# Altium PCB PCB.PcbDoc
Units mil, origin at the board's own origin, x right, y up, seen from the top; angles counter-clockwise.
Board outline 6444.88 x 3495 mil, 2 copper layers (Top Layer, Bottom Layer); 152 components, 81 nets, 447 pads, 87 vias.
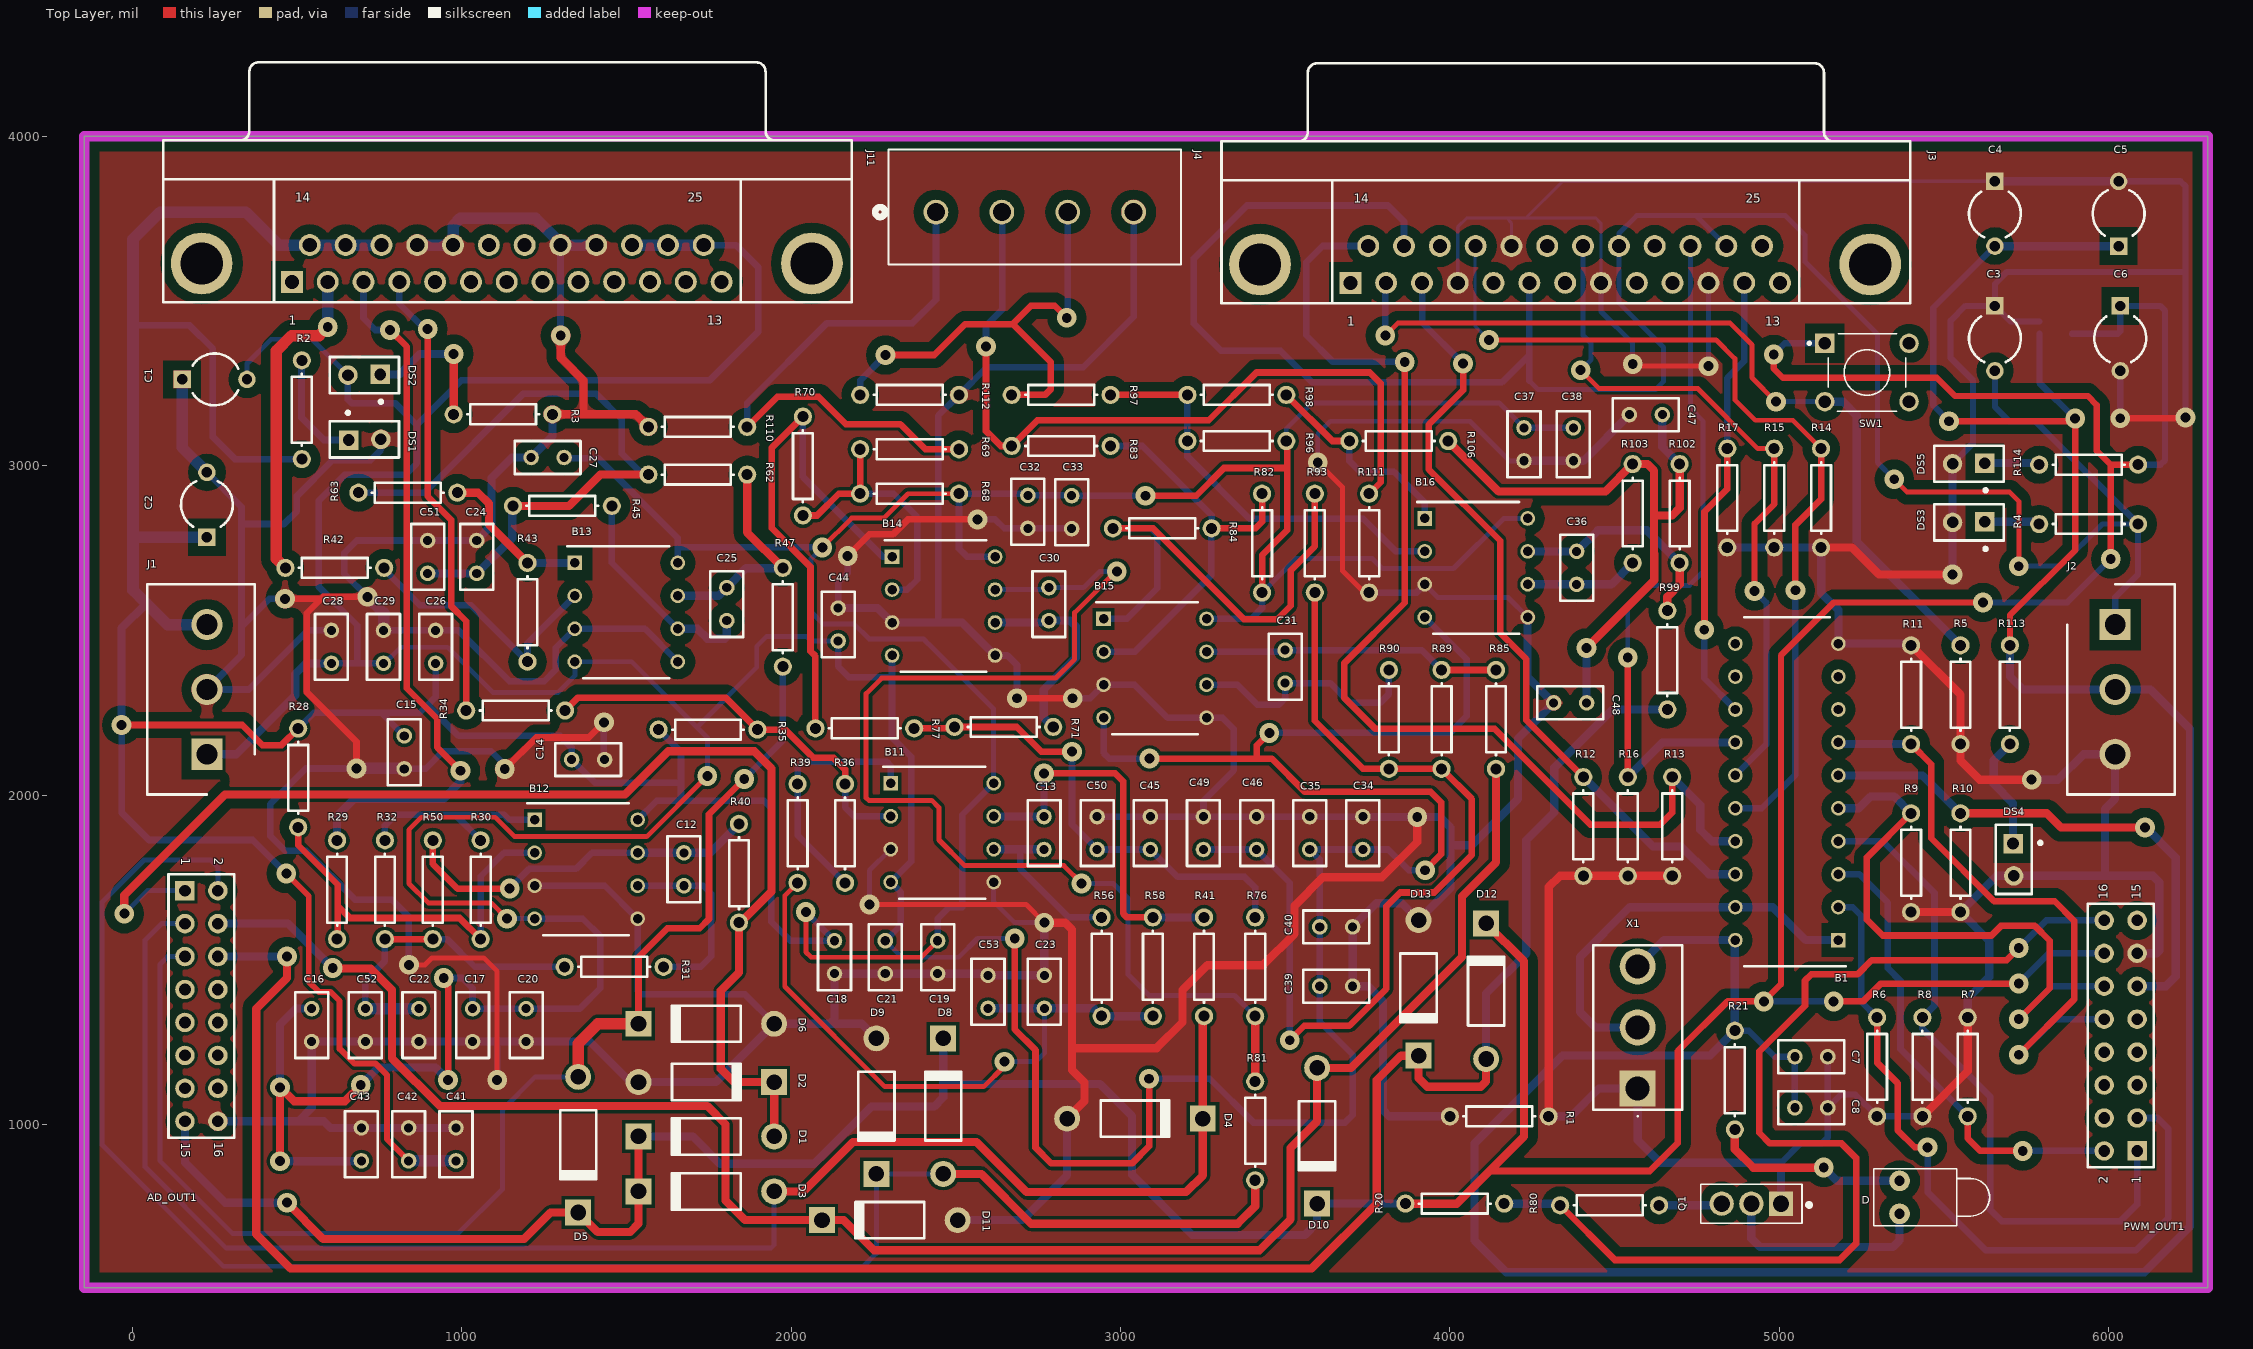
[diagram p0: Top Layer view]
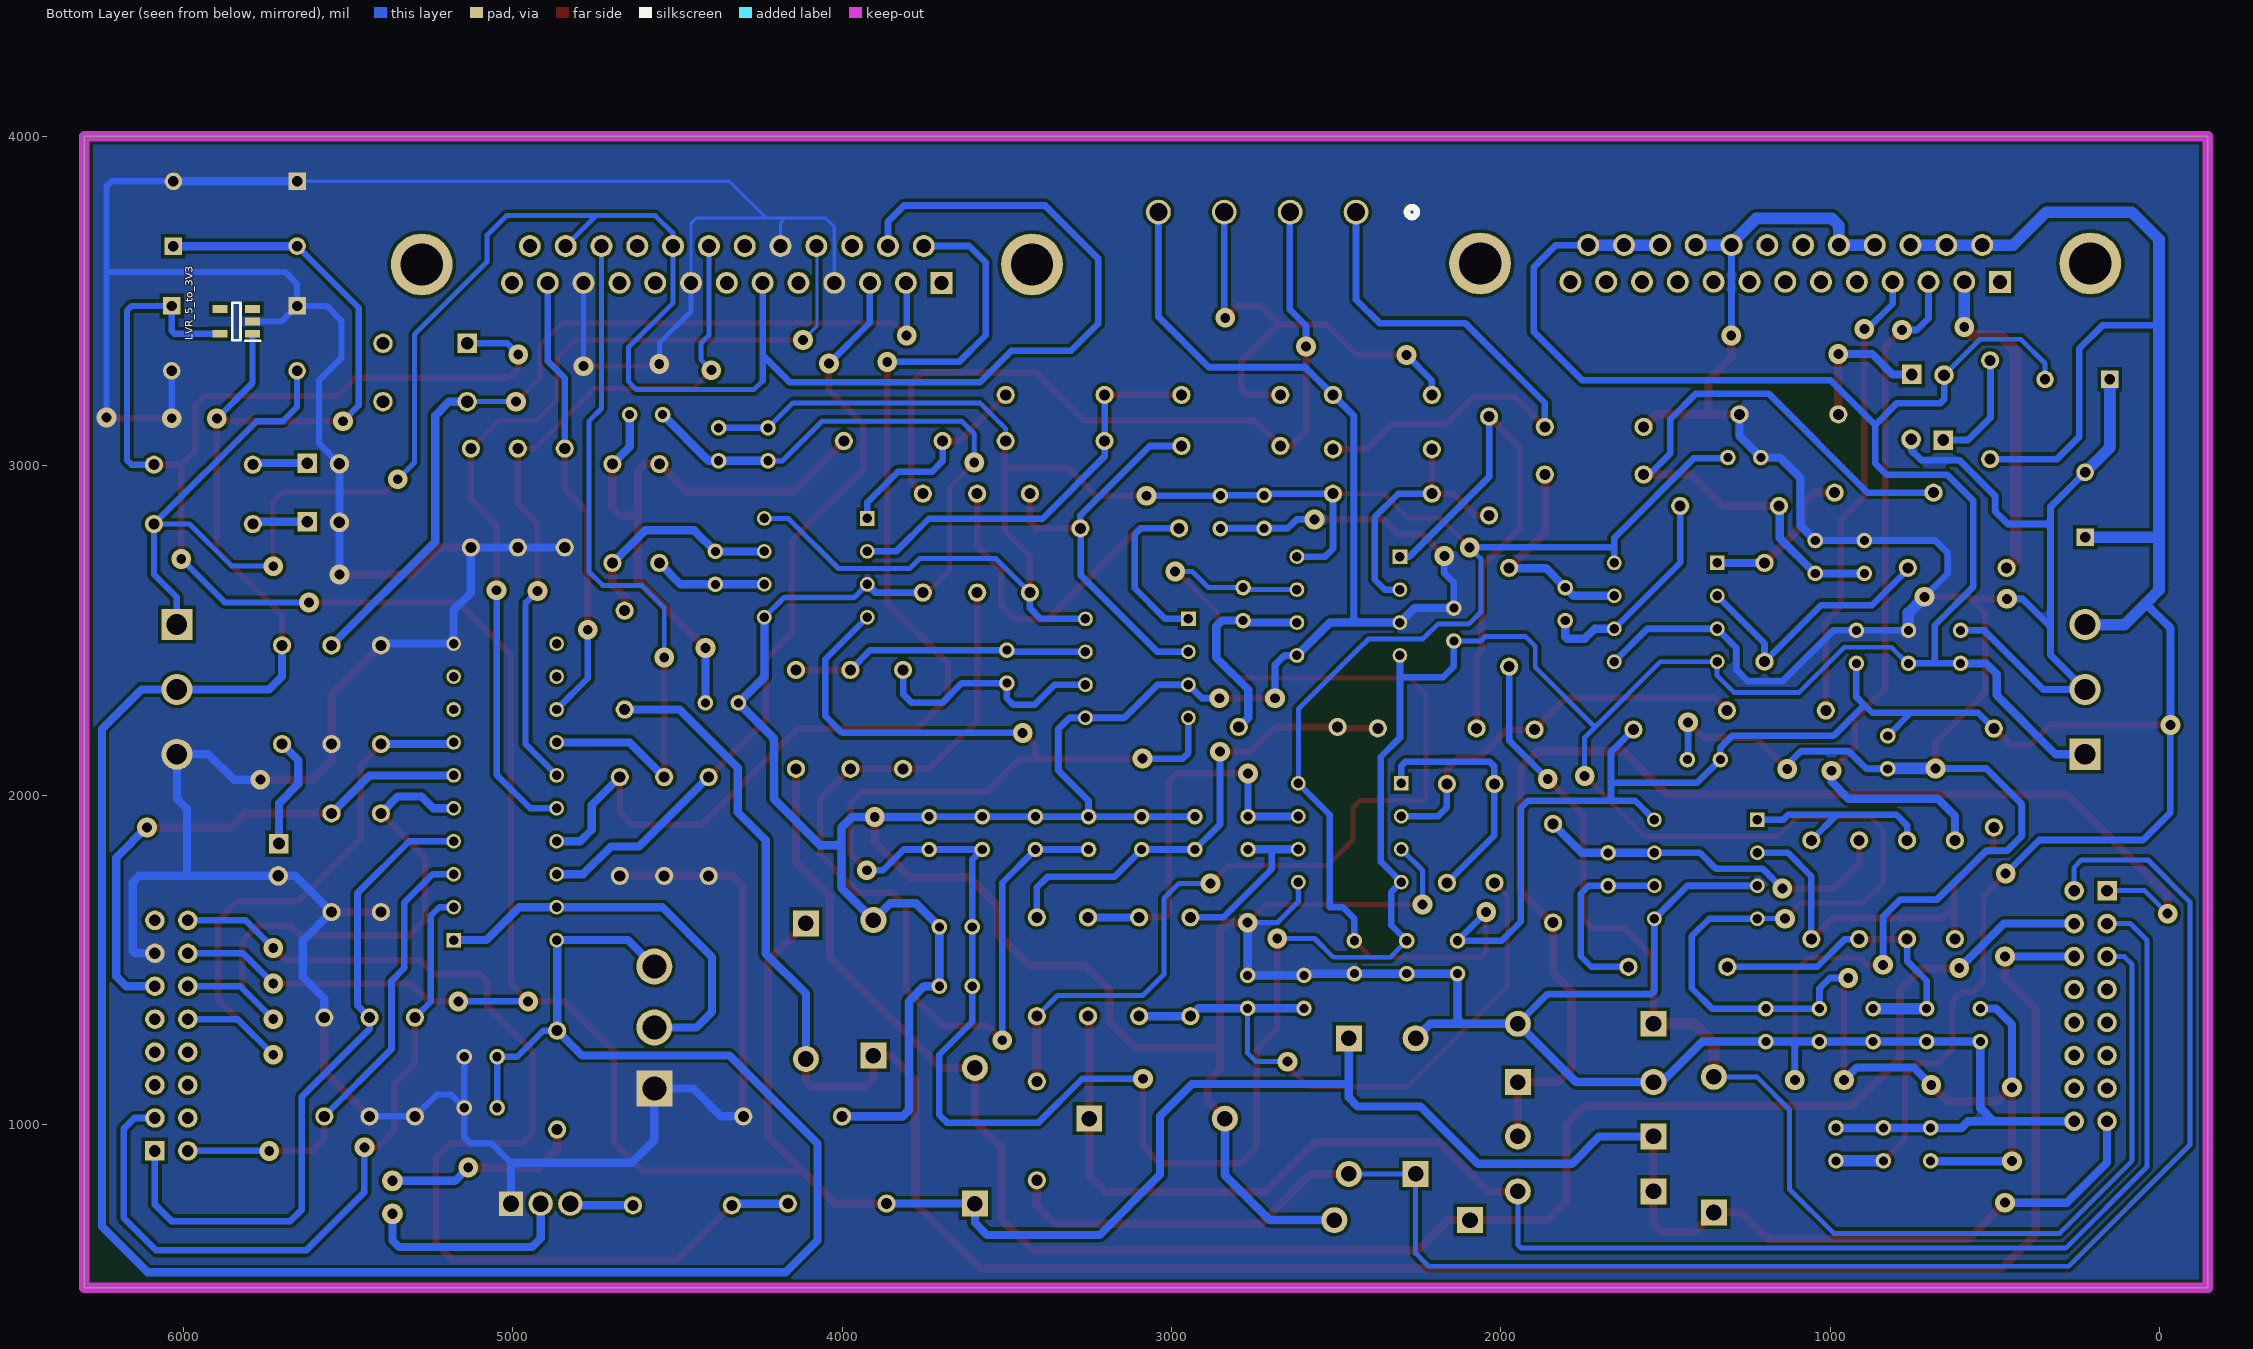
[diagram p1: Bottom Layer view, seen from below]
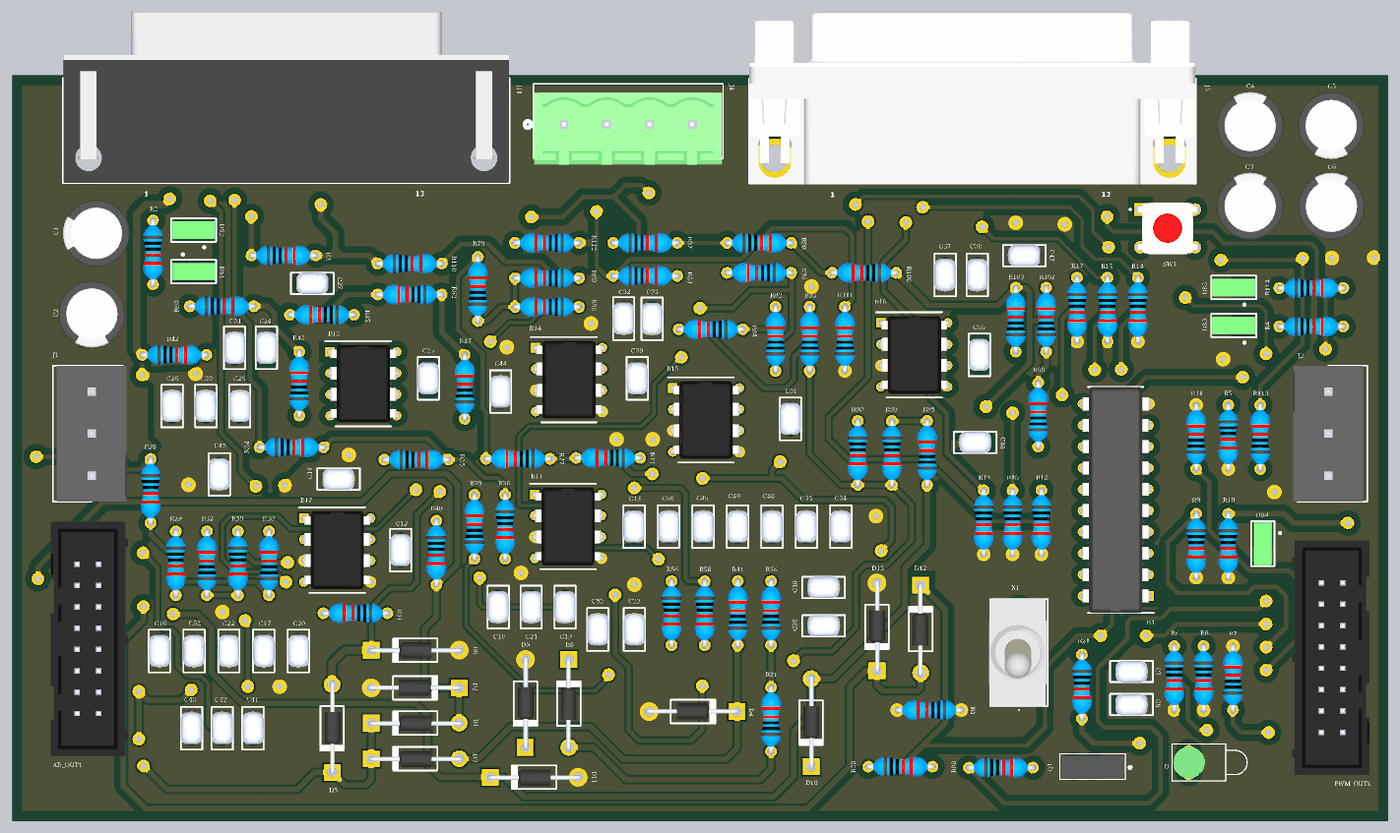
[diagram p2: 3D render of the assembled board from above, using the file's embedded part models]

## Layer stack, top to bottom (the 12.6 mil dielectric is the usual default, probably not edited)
Top Solder: solder mask 0.4, Solder Resist, Dk 3.5
Top Layer: signal copper 1.4
Dielectric 1: dielectric 12.6, FR-4, Dk 4.8
Bottom Layer: signal copper 1.4
Bottom Solder: solder mask 0.4, Solder Resist, Dk 3.5

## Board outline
-144.88,505 6300,505 6300,4000 -144.88,4000

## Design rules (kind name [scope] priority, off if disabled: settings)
Clearance "my clearance" [InNamedPolygon('Top Layer-No Net')] p1: gap=30
Clearance Clearance_1 [(InPadClass('All Pads')) vs (InPadClass('All Pads'))] p2: gap=10
Clearance [All] p3: gap=10
HoleSize [All] p1: absolutevalues=TRUE maxlimit=150 minlimit=1 maxpercent=80.000 minpercent=20.000
PolygonConnect [All] p1: connectstyle=Direct reliefconductorwidth=10 reliefentries=4 polygonreliefangle="90 Angle" airgapwidth=10
RoutingVias [All] p1: holewidth=30 width=60 viastyle="Through Hole" minholewidth=30 minwidth=60 maxholewidth=30 maxwidth=60
SolderMaskExpansion [All] p1: expansion=4
Width [All] p1: maxlimit=50 minlimit=10 preferedwidth=10
29 further rules are at their usual default settings.

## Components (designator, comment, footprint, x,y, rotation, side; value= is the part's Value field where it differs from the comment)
AD_OUT1 "Header 8X2" HDR2X8 160.22,1710 r270 top
B1 "SN74HCT541N" DIP794W53P254L2540H508Q20N 5023,2010 r180 top
B11 "TL082IP" DIP794W53P254L959H508Q8N 2459,1886 r0 top
B12 "TL082IP" DIP794W53P254L959H508Q8N 1378,1775 r0 top
B13 "TL082IP" DIP794W53P254L959H508Q8N 1500,2555 r0 top
B14 "TL082IP" DIP794W53P254L959H508Q8N 2463,2574 r0 top
B15 "TL082IP" DIP794W53P254L959H508Q8N 3105,2385 r0 top
B16 "TL082IP" DIP794W53P254L959H508Q8N 4080,2690 r0 top
C1 "Cap Pol" CAPR5-4X5 250,3262 r0 top
C2 "Cap Pol" CAPR5-4X5 226.97,2881.57 r90 top
C3 "Cap Pol" CAPR5-4X5 5654.5,3386.57 r270 top
C4 "Cap Pol" CAPR5-4X5 5654.5,3765 r270 top
C5 "Cap Pol" CAPR5-4X5 6030,3765 r90 top
C6 "Cap Pol" CAPR5-4X5 6035,3386.57 r270 top
C7 "Cap No Pol" RAD-0.1 5097,1206 r0 top
C8 "Cap No Pol" RAD-0.1 5097,1051 r0 top
C12 "Cap No Pol" RAD-0.1 1675,1775 r270 top
C13 "Cap No Pol" RAD-0.1 2768,1885 r270 top
C14 "Cap No Pol" RAD-0.1 1384,2108 r0 top
C15 "Cap No Pol" RAD-0.1 826,2130 r270 top
C16 "Cap No Pol" RAD-0.1 545,1302 r90 top
C17 "Cap No Pol" RAD-0.1 1033.25,1302 r90 top
C18 "Cap No Pol" RAD-0.1 2132,1508 r270 top
C19 "Cap No Pol" RAD-0.1 2445,1508 r270 top
C20 "Cap No Pol" RAD-0.1 1196,1302 r90 top
C21 "Cap No Pol" RAD-0.1 2286,1508 r90 top
C22 "Cap No Pol" RAD-0.1 870.5,1302 r270 top
C23 "Cap No Pol" RAD-0.1 2769,1403 r90 top
C24 "Cap No Pol" RAD-0.1 1046,2723 r90 top
C25 "Cap No Pol" RAD-0.1 1805,2580 r270 top
C26 "Cap No Pol" RAD-0.1 921,2450 r90 top
C27 "Cap No Pol" RAD-0.1 1261,3025 r180 top
C28 "Cap No Pol" RAD-0.1 605,2450 r270 top
C29 "Cap No Pol" RAD-0.1 763,2450 r270 top
C30 "Cap No Pol" RAD-0.1 2783,2580 r270 top
C31 "Cap No Pol" RAD-0.1 3500,2390 r270 top
C32 "Cap No Pol" RAD-0.1 2719,2860 r270 top
C33 "Cap No Pol" RAD-0.1 2852,2859 r270 top
C34 "Cap No Pol" RAD-0.1 3736,1885 r270 top
C35 "Cap No Pol" RAD-0.1 3574.67,1885 r270 top
C36 "Cap No Pol" RAD-0.1 4385,2690 r270 top
C37 "Cap No Pol" RAD-0.1 4225,3065 r270 top
C38 "Cap No Pol" RAD-0.1 4375,3065 r270 top
C39 "Cap No Pol" RAD-0.1 3655,1420 r180 top
C40 "Cap No Pol" RAD-0.1 3655,1600 r180 top
C41 "Cap No Pol" RAD-0.1 983,940 r90 top
C42 "Cap No Pol" RAD-0.1 839,940 r90 top
C43 "Cap No Pol" RAD-0.1 696,940 r270 top
C44 "Cap No Pol" RAD-0.1 2143,2518 r270 top
C45 "Cap No Pol" RAD-0.1 3090.67,1885 r90 top
C46 "Cap No Pol" RAD-0.1 3413.33,1885 r90 top
C47 "Cap No Pol" RAD-0.1 4595,3155 r180 top
C48 "Cap No Pol" RAD-0.1 4365,2280 r180 top
C49 "Cap No Pol" RAD-0.1 3252,1885 r90 top
C50 "Cap No Pol" RAD-0.1 2929.33,1885 r90 top
C51 "Cap No Pol" RAD-0.1 897,2723 r90 top
C52 "Cap No Pol" RAD-0.1 707.75,1302 r270 top
C53 "Cap No Pol" RAD-0.1 2598,1403 r90 top
D "LED1" LED-1 5365,779.23 r0 top
D1 "Diode BAT54" DO-204AL 1743,964 r180 top
D2 "Diode BAT54" DO-204AL 1743,1129 r0 top
D3 "Diode BAT54" DO-204AL 1743,797 r180 top
D4 "Diode BAT54" DO-204AL 3044,1018 r0 top
D5 "Diode BAT54" DO-204AL 1354,939 r270 top
D6 "Diode BAT54" DO-204AL 1743,1306 r180 top
D8 "Diode BAT54" DO-204AL 2462,1056 r90 top
D9 "Diode BAT54" DO-204AL 2259,1056 r270 top
D10 "Diode BAT54" DO-204AL 3597,966 r270 top
D11 "Diode BAT54" DO-204AL 2300,710 r180 top
D12 "Diode BAT54" DO-204AL 4110,1405 r90 top
D13 "Diode BAT54" DO-204AL 3905,1415 r270 top
DS1 "Lamp" PIN2 655,3080 r0 top
DS2 "Lamp" PIN2 755,3275 r180 top
DS3 "Lamp" PIN2 5626,2828 r180 top
DS4 "Lamp" PIN2 5711.64,1855 r270 top
DS5 "Lamp" PIN2 5626,3006 r180 top
J1 "CTB9302_3" SHDR3W100P0X500_1X3_1620X830X1230P 226.97,2124 r90 top
J2 "CTB9302_3" SHDR3W100P0X500_1X3_1620X830X1230P 6019.41,2517.7 r270 top
J3 "D Female Connector 25" DSUB1.385-2H25B 4350,3985 r0 top
J4 "1755752" CONN_1924321 3040,3770 r0 top
J11 "D Connector 25" DSUB1.385-2H25A 1137.13,3987.99 r0 top
LVR_5_to_3V3 "ADP151AUJZ-3.3-R7" SOT95P280X100-5N 5839,3438 r0 bottom
PWM_OUT1 "Header 8X2" HDR2X8 6086.16,919.97 r90 top
Q1 "BD135" TO229P780X300X2000-3 5005.31,760 r180 top
R1 "Res1" AXIAL-0.3 4150,1025 r0 top
R2 "Res1" AXIAL-0.3 515,3170 r90 top
R3 "Res1" AXIAL-0.3 1126,3156 r180 top
R4 "Res1" AXIAL-0.3 5939,2823 r180 top
R5 "Res1" AXIAL-0.3 5550,2305 r90 top
R6 "Res1" AXIAL-0.3 5297,1175 r90 top
R7 "Res1" AXIAL-0.3 5572,1175 r270 top
R8 "Res1" AXIAL-0.3 5434.5,1175 r90 top
R9 "Res1" AXIAL-0.3 5400,1795 r90 top
R10 "Res1" AXIAL-0.3 5550,1795 r90 top
R11 "Res1" AXIAL-0.3 5400,2305 r270 top
R12 "Res1" AXIAL-0.3 4405,1905 r90 top
R13 "Res1" AXIAL-0.3 4675,1905 r90 top
R14 "Res1" AXIAL-0.3 5127,2902 r90 top
R15 "Res1" AXIAL-0.3 4984.5,2902 r90 top
R16 "Res1" AXIAL-0.3 4540,1905 r90 top
R17 "Res1" AXIAL-0.3 4842,2902 r90 top
R20 "Res1" AXIAL-0.3 4015,760 r180 top
R21 "Res1" AXIAL-0.3 4865,1135 r90 top
R28 "Res1" AXIAL-0.3 504,2052.38 r90 top
R29 "Res1" AXIAL-0.3 622,1713 r90 top
R30 "Res1" AXIAL-0.3 1058,1713 r270 top
R31 "Res1" AXIAL-0.3 1463,1479 r0 top
R32 "Res1" AXIAL-0.3 767.33,1713 r270 top
R34 "Res1" AXIAL-0.3 1164,2257 r180 top
R35 "Res1" AXIAL-0.3 1748,2199 r180 top
R36 "Res1" AXIAL-0.3 2164,1884 r90 top
R39 "Res1" AXIAL-0.3 2020,1884 r270 top
R40 "Res1" AXIAL-0.3 1842,1763 r90 top
R41 "Res1" AXIAL-0.3 3253.67,1479 r270 top
R42 "Res1" AXIAL-0.3 615,2690 r180 top
R43 "Res1" AXIAL-0.3 1200,2555 r270 top
R45 "Res1" AXIAL-0.3 1306,2878 r0 top
R47 "Res1" AXIAL-0.3 1975,2540 r270 top
R50 "Res1" AXIAL-0.3 912.67,1713 r90 top
R56 "Res1" AXIAL-0.3 2943,1479 r90 top
R58 "Res1" AXIAL-0.3 3098.33,1479 r90 top
R62 "Res1" AXIAL-0.3 1717,2973 r0 top
R63 "Res1" AXIAL-0.3 837,2918 r180 top
R68 "Res1" AXIAL-0.3 2360,2915 r0 top
R69 "Res1" AXIAL-0.3 2360,3050 r0 top
R70 "Res1" AXIAL-0.3 2036,2999 r270 top
R71 "Res1" AXIAL-0.3 2646,2207 r0 top
R76 "Res1" AXIAL-0.3 3409,1479 r270 top
R77 "Res1" AXIAL-0.3 2224,2203 r0 top
R80 "Res1" AXIAL-0.3 4485,755 r180 top
R81 "Res1" AXIAL-0.3 3409,981 r270 top
R82 "Res1" AXIAL-0.3 3430,2765 r270 top
R83 "Res1" AXIAL-0.3 2820,3060 r180 top
R84 "Res1" AXIAL-0.3 3127,2810 r0 top
R85 "Res1" AXIAL-0.3 4140,2230 r270 top
R89 "Res1" AXIAL-0.3 3975,2230 r90 top
R90 "Res1" AXIAL-0.3 3815,2230 r90 top
R93 "Res1" AXIAL-0.3 3590,2765 r270 top
R96 "Res1" AXIAL-0.3 3353.33,3075 r0 top
R97 "Res1" AXIAL-0.3 2820,3215 r180 top
R98 "Res1" AXIAL-0.3 3353.33,3215 r180 top
R99 "Res1" AXIAL-0.3 4660,2410 r270 top
R102 "Res1" AXIAL-0.3 4697.5,2855 r270 top
R103 "Res1" AXIAL-0.3 4555,2855 r270 top
R106 "Res1" AXIAL-0.3 3845,3075 r0 top
R110 "Res1" AXIAL-0.3 1717,3118 r180 top
R111 "Res1" AXIAL-0.3 3755,2765 r270 top
R112 "Res1" AXIAL-0.3 2360,3215 r0 top
R113 "Res1" AXIAL-0.3 5700,2305 r270 top
R114 "Res1" AXIAL-0.3 5939,3003 r180 top
SW1 "1825910-6" SW_1825910-6-4 5266,3283 r0 top
X1 "1MS1T1B1M2QES" 1MS1T1B1M2QES 4570,1109.92 r0 top

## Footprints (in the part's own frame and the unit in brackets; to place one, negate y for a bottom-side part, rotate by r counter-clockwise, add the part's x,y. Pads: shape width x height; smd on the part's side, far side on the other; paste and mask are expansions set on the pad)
1MS1T1B1M2QES [mm]
  rect 2.775x2.775 hole 1.85: 1(0,0)
  round 2.775 hole 1.85: 2(0,4.7) 3(0,9.4)
  silkscreen extent -3.43,-2.2 3.43,11.05, body extent -3.56,-1.65 3.3,11.05, height 27.73
AXIAL-0.3 [mm]
  round 1.4 hole 0.85: 1(-3.81,0) 2(3.81,0)
  silkscreen extent -2.77,-0.76 2.77,0.76, body extent -4.11,-1.2 4.11,1.2, height 2.6
CAPR5-4X5 [mm]
  rect 1.35x1.35 hole 0.8: 1(-2.5,0)
  round 1.35 hole 0.8: 2(2.5,0)
  silkscreen extent -1.69,-2 1.82,2, body extent -4,-4.05 4,3.95, height 11.75
CONN_1924321 [mil]
  round 75 / inner round 60 / far side round 75 hole 55 paste-37.5 mask+0: 1(-600,0) 2(-400,0) 3(-200,0) 4(0,0)
  silkscreen extent -784,-159 144,190, body extent -740,-189 139,150, height 492
DIP794W53P254L959H508Q8N [mm]
  rect 1.13x1.13 / inner round 1.13 / far side rect 1.13x1.13 hole 0.73: 1(-3.97,3.81)
  round 1.13 hole 0.73: 2(-3.97,1.27) 3(-3.97,-1.27) 4(-3.97,-3.81) 5(3.97,-3.81) 6(3.97,-1.27) 7(3.97,1.27) 8(3.97,3.81)
  silkscreen extent -4.53,-5.08 3.3,5.08, body extent -4.1,-4.64 4.1,4.64, height 4.21
DIP794W53P254L2540H508Q20N [mm]
  rect 1.13x1.13 / inner round 1.13 / far side rect 1.13x1.13 hole 0.73: 1(-3.97,11.43)
  round 1.13 hole 0.73: 2(-3.97,8.89) 3(-3.97,6.35) 4(-3.97,3.81) 5(-3.97,1.27) 6(-3.97,-1.27) 7(-3.97,-3.81) 8(-3.97,-6.35) 9(-3.97,-8.89) 10(-3.97,-11.43) 11(3.97,-11.43) 12(3.97,-8.89) 13(3.97,-6.35) 14(3.97,-3.81) 15(3.97,-1.27) 16(3.97,1.27) 17(3.97,3.81) 18(3.97,6.35) 19(3.97,8.89) 20(3.97,11.43)
  silkscreen extent -4.53,-13.46 3.3,13.46, body extent -3.94,-13.46 3.94,13.46, height 5.18
DO-204AL [mm]
  round 2 hole 1.2: 1(-5.23,0)
  rect 2x2 hole 1.2: 2(5.23,0)
  silkscreen extent -2.65,-1.4 2.75,1.4, body extent -5.66,-0.92 5.56,0.99, height 2.04
DSUB1.385-2H25A [mm]
  rect 1.69x1.69 hole 1.09: 1(-16.566,-10.92)
  round 1.69 hole 1.09: 2(-13.805,-10.92) 3(-11.044,-10.92) 4(-8.283,-10.92) 5(-5.522,-10.92) 6(-2.761,-10.92) 7(0,-10.92) 8(2.761,-10.92) 9(5.522,-10.92) 10(8.283,-10.92) 11(11.044,-10.92) 12(13.805,-10.92) 13(16.566,-10.92) 14(-15.185,-8.08) 15(-12.424,-8.08) 16(-9.663,-8.08) 17(-6.902,-8.08) 18(-4.141,-8.08) 19(-1.38,-8.08) 20(1.381,-8.08) 21(4.142,-8.08) 22(6.903,-8.08) 23(9.664,-8.08) 24(12.425,-8.08) 25(15.186,-8.08)
  round 4.76 hole 3.26: 26(-23.526,-9.5) 27(23.526,-9.5)
  silkscreen extent -26.5,-12.5 26.6,6, body extent -26.47,-12.47 26.57,7.85, height 13.49
DSUB1.385-2H25B [mm]
  rect 1.69x1.69 hole 1.09: 1(-16.566,-10.92)
  round 1.69 hole 1.09: 2(-13.805,-10.92) 3(-11.044,-10.92) 4(-8.283,-10.92) 5(-5.522,-10.92) 6(-2.761,-10.92) 7(0,-10.92) 8(2.761,-10.92) 9(5.522,-10.92) 10(8.283,-10.92) 11(11.044,-10.92) 12(13.805,-10.92) 13(16.566,-10.92) 14(-15.185,-8.08) 15(-12.424,-8.08) 16(-9.663,-8.08) 17(-6.902,-8.08) 18(-4.141,-8.08) 19(-1.38,-8.08) 20(1.381,-8.08) 21(4.142,-8.08) 22(6.903,-8.08) 23(9.664,-8.08) 24(12.425,-8.08) 25(15.186,-8.08)
  round 4.76 hole 3.26: 26(-23.526,-9.5) 27(23.526,-9.5)
  silkscreen extent -26.5,-12.5 26.6,6, body extent -26.49,-12.58 26.55,7.92, height 12.55
HDR2X8 [mm]
  rect 1.5x1.5 hole 0.9: 1(0,0)
  round 1.5 hole 0.9: 2(0,2.54) 3(2.54,0) 4(2.54,2.54) 5(5.08,0) 6(5.08,2.54) 7(7.62,0) 8(7.62,2.54) 9(10.16,0) 10(10.16,2.54) 11(12.7,0) 12(12.7,2.54) 13(15.24,0) 14(15.24,2.54) 15(17.78,0) 16(17.78,2.54)
  silkscreen extent -1.27,-1.27 19.05,3.81, body extent -5.05,-3.18 22.89,6.02, height 9.46
LED-1 [mm]
  round 1.6 hole 0.8: 1(0,1.27) 2(0,-1.27)
  silkscreen extent -2,-2.2 6.95,2.2, body extent -1.87,-1.9 1.93,1.9, height 5.3
PIN2 [mm]
  rect 1.5x1.5 hole 0.9: 1(0.051,-0.051)
  round 1.5 hole 0.9: 2(2.54,0)
  silkscreen extent -1.4,-1.4 3.94,2.17, body extent -1.23,-1.05 3.82,1.05, height 8
RAD-0.1 [mm]
  round 1.2 hole 0.7: 1(-1.27,0) 2(1.27,0)
  silkscreen extent -2.54,-1.27 2.54,1.27, body extent -1.9,-1.3 1.9,1.24, height 6.99
SHDR3W100P0X500_1X3_1620X830X1230P [mm]
  rect 2.4x2.4 / inner round 2.4 / far side rect 2.4x2.4 hole 1.6: 1(0,0)
  round 2.4 hole 1.6: 2(5,0) 3(10,0)
  silkscreen extent -3.1,-3.7 13.1,4.6, body extent -3.1,-4.18 13.1,4.12, height 12.3
SOT95P280X100-5N [mm]
  rect 1.15x0.6 smd: 1(-1.25,0.95) 2(-1.25,0) 3(-1.25,-0.95) 4(1.25,-0.95) 5(1.25,0.95)
  silkscreen extent -1.83,-1.45 0.33,1.5, body extent -1.4,-1.45 1.4,1.45, height 1
SW_1825910-6-4 [mm]
  rect 1.498x1.498 / inner round 1.498 / far side rect 1.498x1.498 hole 0.99: 1(-3.25,2.25)
  round 1.498 hole 0.99: 2(3.25,2.25) 3(-3.25,-2.25) 4(3.25,-2.25)
  silkscreen extent -4.54,-3 3,3, body extent -3.9,-2.97 3.9,3.02, height 7.08
TO229P780X300X2000-3 [mm]
  rect 1.875x1.875 / inner round 1.875 / far side rect 1.875x1.875 hole 1.25: 1(0,0)
  round 1.875 hole 1.25: 2(2.29,0) 3(4.58,0)
  silkscreen extent -2.31,-1.5 6.19,1.5, body extent -1.51,-1.27 6.09,1.38, height 13.2

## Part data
AD_OUT1 PWM_OUT1: "Header, 8-Pin, Dual row"
B1: "Octal Buffers and Line Drivers With 3-State Outputs"
B11 B12 B13 B14 B15 B16: "TL082IP, Dual Operational Amplifier 3MHz, 8-Pin PDIP"
C1 C2 C3 C4 C5 C6: "Capacitor"
C7 C8 C12 C13 C14 C15 C16 C17 C18 C19 C20 C21 C22 C23 C24 C25 C26 C27 C28 C29 C30 C31 C32 C33 C34 C35 C36 C37 C38 C39 C40 C41 C42 C43 C44 C45 C46 C47 C48 C49 C50 C51 C52 C53: "Polarized Capacitor (Radial)"
D: "Typical RED GaAs LED"
D1 D2 D3 D4 D5 D6 D8 D9 D10 D11 D12 D13: library part "Diode Zener", "Zener"
DS1 DS2 DS3 DS4 DS5: "Incandescent Bulb"
J1 J2: "RS PRO 5mm Pitch Vertical PCB Terminal Block, PCB Header, PCB Mount, 3 Way"
J3 J11: "Receptacle Assembly, 25 Position, Right Angle"
J4: "No Description Available"
LVR_5_to_3V3: "Analog Devices ADP151AUJZ-3.3-R7, Single Linear Voltage Regulator, 200mA 3.3 V, +/-2.5%, 5-Pin TSOT"
Q1: "TRANSISTOR, NPN, TO-126; Transistor Polarity:NPN; Collector Emitter Voltage V(br)ceo:45V; Power Dissipation Pd:12.5W; DC Collector Current:1A; DC Current Gain hFE:40; Transistor Case Style:TO-126; No. of Pins:3; SVHC:No SVHC (18-Jun-2012); Collector Emitter Voltage Vces:500mV; Continuous Collector Current Ic Max:1A; Current Ic Continuous a Max:1A; Current Ic hFE:150mA; Full Power Rating Temperature:25°C; Hfe Min:40; No. of Transistors:1; Package / Case:TO-126; Power Dissipation Pd:12.5W; Power Dissipation Ptot Max:12.5W; Termination Type:Through Hole; Voltage Vcbo:45V"
R1 R2 R3 R4 R5 R6 R7 R8 R9 R10 R11 R12 R13 R14 R15 R16 R17 R20 R21 R28 R29 R30 R31 R32 R34 R35 R36 R39 R40 R41 R42 R43 R45 R47 R50 R56 R58 R62 R63 R68 R69 R70 R71 R76 R77 R80 R81 R82 R83 R84 R85 R89 R90 R93 R96 R97 R98 R99 R102 R103 R106 R110 R111 R112 R113 R114: "Resistor"
SW1: "Switch Push Button OFF (ON) SPST Round Button 0.05A 24VDC Momentary Contact PC Pins Thru-Hole"
X1: "Toggle Switches SWITCH TOGGLE SPDT"

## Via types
v1: diameter 60, hole 30, Top Layer to Bottom Layer, 87 vias

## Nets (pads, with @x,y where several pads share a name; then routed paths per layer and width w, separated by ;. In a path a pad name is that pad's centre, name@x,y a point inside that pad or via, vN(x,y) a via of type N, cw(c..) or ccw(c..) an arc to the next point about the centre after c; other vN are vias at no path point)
+3V3: AD_OUT1.15 C6.1 D1.2 D3.2 D5.2 D8.2 D10.2 D12.2 LVR_5_to_3V3.5 PWM_OUT1.14 R20.2 R114.1 SW1.1 | length 13280.7
  Top Layer w19: v1(4953,1374) 5005,1426 5005,2424 5166,2585 v1(5618,2585) ; v1(4983,3338) 4983,3295 5011,3267 5478,3267 5533,3212 5936,3212 5964,3184 5964,3045 6006,3003 ; v1(6006,2717) 6006,3003 ; R114.1 6006,3003
  Top Layer w20: 4120,859 4607,859 4692,944 4692,1223 4843,1374 v1(4953,1374) ; v1@5168,1377 v1(5165,1374) 5254.43,1374 5308.4,1427.98 v1(5727,1427.98)
  Top Layer w25: v1(470,763) 580,653 1190,653 1270.09,733.09 D5.2 1413.09,674 1512,674 1537.09,699.09 D3.2 D1.2 ; R20.2 4021,760 4120,859 4225,964 4225,1495.91 D12.2
  Bottom Layer w19: v1(4983,3338) 5016.58,3371.58 SW1.1 ; v1(5618,2585) 5874,2585 v1(6006,2717) ; LVR_5_to_3V3.5 6027.6,3400.6 6035,3408 C6.1 6156,3485 6171,3470 6171,3017 6157,3003 R114.1
  Bottom Layer w20: v1(4953,1374) v1(5165,1374) ; v1(5727,1427.98) 5818.99,1519.97 PWM_OUT1.14
  Bottom Layer w25: AD_OUT1.15 160.22,884.77 281.99,763 v1(470,763) ; D1.2 1702,964 1785,881 2070,881 2244,1055 2435,1055 2462,1082 D8.2 ; 2462,1123 2938,1123 3035,1026 3035,848 3218,665 3560,665 3597,702 D10.2 3864.91,760.09 R20.2
+5V: B1.20 C4.2 C5.1 C7.1 C8.1 J2.2 LVR_5_to_3V3.1 R21.2 R113.1 X1.3 | length 9152.8
  Top Layer w19: v1(5515,3135) 5890,3135 v1(5898,3143) 5898,2744 5700,2546 R113.1
  Bottom Layer w19: v1(5515,3135) 5467,3183 5467,3479.08 C4.2 ; LVR_5_to_3V3.1 5789.79,3251.21 v1(5898,3143)
  Bottom Layer w20: R21.2 4907,1285 4986,1206 C7.1 C8.1
  Bottom Layer w25: X1.3 4650,1560 B1.20 4865,1558.3 R21.2 4790,1210 4342,1210 4075,943 4075,648 4171,552 6108.5,552 6247,690.5 6247,2201 6127.15,2320.85 J2.2 5739.15,2320.85 5700,2360 R113.1 ; C4.2 C5.1
+12V: C3.2 J2.1 J3.6 J3.15 J3.21 J3.24 R4.1 | length 6994
  Top Layer w15: v1(5349,2959) 5388,2920 5699,2920 5727,2892 v1(5727,2695)
  Bottom Layer w15: 4241.3,3257.7 4268,3231 4624,3231 4649,3256 4649,3359 4513.05,3494.95 J3.21 4513.05,3705.05 4567,3759 4747.04,3759 ; J3.24 4747.04,3759 ; v1(5349,2959) 5298,3010 5298,3399 5078,3619 5078,3700 5019,3759 4747.04,3759 ; v1(5727,2695) 5853,2695 5981,2823 R4.1
  Bottom Layer w19: C3.2 5654.5,3178.5 5698,3135 5777,3135 R4.1 6089,2670 6019.41,2600.41 J2.1
  Bottom Layer w20: J3.15 3860.85,3741.15 3812,3790 3384,3790 3223,3629 3223,3431 3305,3349 3486,3349 3582,3253 4158,3253 4241.3,3336.3 ; 4241.3,3257.7 J3.6
+15V: B11.8 B12.8 B13.8 B14.8 B15.8 B16.8 C2.1 C14.1 C15.1 C18.1 C19.1 C26.1 C27.1 C32.1 C33.1 C37.1 C38.1 C41.1 C42.1 J1.3 J11.14 J11.15 J11.16 R2.1 R28.2 R35.2 R68.2 R82.2 R96.2 | length 16805.4
  Top Layer w15: v1(2045,1645) 2045,1524 2061,1508 2395,1508 C19.1 ; v1(2095,2752) 2184,2841 2281,2841 2355,2915 R68.2
  Top Layer w18: v1(468,1762) 536,1694 536,1434 567,1403 602,1403 630,1375 630,1230 675,1185 739,1185 773,1151 773,956 C42.1
  Top Layer w20: v1(-32,2213) 334,2213 395,2152 453.62,2152 R28.2 ; v1(3076,2909) 3230,2909 3314,2993 3506,2993 ; R82.2 3430,2728 3506,2804 3506,2993 ; R96.2 3506,3072.33 3506,2993
  Bottom Layer w15: v1(2095,2752) 2061,2718 2061,2556 2098,2519 2192,2519 2237,2474 2402,2474 2417,2459 2418,2459 2615.3,2261.7 B11.8 ; R82.2 3533,2718 3765,2718 3795,2688 4011,2688 4163,2840 B16.8 ; R96.2 3503.33,3112.33 3582,3191 4149,3191 C37.1
  Bottom Layer w20: v1(-32,2213) -32,1947 51,1864 366,1864 v1(468,1762) ; 2.5,3426 174,3426 245,3355 245,3087 312,3020 R2.1 ; R28.2 551.62,2250 756,2250 ; C15.1 756,2250 ; C26.1 921,2298 897,2274 ; C27.1 1313,3023 1414,3023 1656.3,2780.7 1656.3,2757 ; B12.8 1592.3,1983 1666,1983 ; R35.2 1666,2131 1666,2038 ; B13.8 1656.3,2757 ; v1(2045,1645) C18.1 1998,1558 1940,1616 1940,1961 1918,1983 1666,1983 ; v1(2095,2752) 1661.3,2752 1656.3,2757 ; C19.1 2445,1625 2480,1660 2520,1660 2520,1940.7 B11.8 ; B14.8 2534,2724 2510,2748 R68.2 2714,2915 C32.1 2851,2910 C33.1 v1(3076,2909) ; B15.8 3397,2535 3430,2568 R82.2 ; C37.1 C38.1 ; 756,2250 873,2250 897,2274 ; 897,2274 991,2180 1299,2180 1334,2145 C14.1 1404,2038 1666,2038 ; 1666,1983 1666,2038
  Bottom Layer w25: v1(-32,2213) -32,2507 43,2582
  Bottom Layer w35: 2.5,2622.5 43,2582 107.3,2517.7 J1.3 ; 2.5,2625.5 2.5,2780 ; C2.1 5.65,2783.15 2.5,2780 ; J11.16 J11.15 J11.14 445.12,3669.88 345,3770 85,3770 2.5,3687.5 2.5,3426 2.5,2780 ; C42.1 C41.1
-15V: B11.4 B12.4 B13.4 B14.4 B15.4 B16.4 C1.2 C16.2 C17.2 C20.2 C21.2 C28.2 C29.2 C34.2 C35.2 C39.2 C40.2 C43.2 C44.2 DS2.2 J1.1 J11.23 J11.24 J11.25 | length 17663.8
  Top Layer w15: v1(1138,1625) 1090,1673 899,1673 840,1732 840,1895 878,1933 1102,1933 1161,1874 1562,1874 v1(1746,2058)
  Top Layer w20: v1(946,1445) 946,1431 959,1418 v1(959,1135) ; v1(2679,1565) 2679,1289 2742,1226 2742,930 2790,882 3035,882 3087,934 v1(3087,1139) ; v1(3088,2111) 3414,2111 ; v1(3452,2189) 3414,2151 3414,2111 ; v1(3925,1772) 3974,1821 3974,1978 3942,2010 3560,2010 3459,2111 3414,2111
  Top Layer w25: v1(449,889) v1(449,1113) 491,1071 646,1071 694,1119 v1(694,1120)
  Bottom Layer w15: C1.2 348.43,3310.43 422,3384 546,3384 DS2.2 ; C29.2 766,2400 815,2449 958,2449 1096,2311 1292,2311 1343.7,2362.7 B13.4 1516,2405 1714.5,2206.5 ; v1(1138,1625) B12.4 ; v1(1746,2058) 1746,2175 1714.5,2206.5 ; C44.2 2061,2468 2047,2482 1926,2482 1896,2452 1896,2388 1714.5,2206.5 ; C21.2 2336,1508 2509,1508 2566,1565 v1(2679,1565)
  Bottom Layer w20: C28.2 683,2400 ; DS2.2 655,3201 666,3190 798,3190 864,3124 ; C29.2 683,2400 ; v1(946,1445) 1002,1445 1033.25,1413.75 C17.2 C20.2 1359,1352 1421,1414 1421,1572 1368,1625 B12.4 ; J11.25 1833.12,3669.88 1901,3602 1901,3407 1753,3259 999,3259 864,3124 ; C44.2 2143,2391 2176,2358 2306.44,2358 ; C21.2 2333,1605 2333,1705.7 B11.4 2364.94,1798.24 2364.94,2116.51 2306.44,2175.02 2306.44,2358 ; B14.4@2306.44,2423.74 2306.44,2358 ; B15.4 2948.7,2128.3 2966,2111 v1(3088,2111) ; v1(3087,1139) 3271,1139 3404,1006 3682,1006 3705,1029 3705,1212 3605,1312 C39.2 C40.2 3605,1804.67 C35.2 C34.2 3813,1835 3876,1772 v1(3925,1772) ; v1(3452,2189) 4000,2189 4051,2240 4051,2412.7 B16.4 ; 683,2400 683,2516 566,2633 566,2893 645,2972 829,2972 864,3007 864,3124
  Bottom Layer w25: J1.1 316,2124 495,2303 495,2367 528,2400 C28.2 ; v1(449,889) 695,889 C43.2 ; v1(449,1113) 449,1304 497,1352 C16.2 ; v1(694,1120) 747,1173 921,1173 v1(959,1135)
  Bottom Layer w35: J11.23 J11.24 J11.25
CURRENT_SENSOR_A_TO_ADC: AD_OUT1.1 D1.1 D2.2 R40.1 | length 3758.1
  Top Layer w25: v1(-23.68,1640.32) -23.68,1696.32 282,2002 1496,2002 1627,2133 1889,2133 1941,2081 1941,1707 1847,1613 R40.1 1842,1462 1787,1407 1787,1169 1827,1129 D2.2 D1.1
  Bottom Layer w15: v1(-23.68,1640.32) 46,1710 AD_OUT1.1
CURRENT_SENSOR_A_TO_FILTER: B12.1 R30.1 R32.1 | length 630.2
  Bottom Layer w20: R32.1 767.33,1908.33 800,1941 980,1941 ; R30.1 980,1941 ; B12.1 1144,1925 1128,1941 980,1941
CURRENT_SENSOR_B_TO_ADC: AD_OUT1.3 D3.1 D4.2 R41.2 | length 4940.4
  Top Layer w25: D3.1 2038,797 2188,947 2563,947 2715,795 3199,795 3249.91,845.91 D4.2 3249.91,1325.24 R41.2
  Bottom Layer w15: AD_OUT1.3 89,1610 39,1560 39,871.64 285.71,624.93 1938.93,624.93 1948.91,634.91 D3.1
CURRENT_SENSOR_B_TO_FILTER: B11.1 R36.1 R39.1 | length 759.8
  Bottom Layer w20: R36.1 2020,1878 R39.1 2020,2087 2034.56,2101.56 2191.98,2101.56 2192.54,2101 2291,2101 2302.7,2089.3 B11.1
CURRENT_SENSOR_OUTPUT_A: J11.3 R29.2 | length 2157.6
  Top Layer w20: v1(783,3412) 833.38,3361.62 833.38,2324.62 926,2232 926,2145 v1(997,2074)
  Bottom Layer w20: J11.3 702.32,3447.68 738,3412 v1(783,3412)
  Bottom Layer w25: R29.2 622,1937 674,1989 945,1989 997,2041 v1(997,2074)
CURRENT_SENSOR_OUTPUT_B: J11.4 R34.2 | length 1390.4
  Top Layer w20: v1(897,3415) 897,2907 968,2836 968,2574 1014,2528 R34.2
  Bottom Layer w20: J11.4 811.02,3491.98 888,3415 v1(897,3415)
DC-LINK_SENSOR_OUTPUT: J11.2 R42.2 | length 992.6
  Top Layer w35: R42.2 438,2717 438,3349.15 483.91,3395.06 567.3,3395.06 v1(593.62,3421.38)
  Bottom Layer w35: v1(593.62,3421.38) J11.2
DC-LINK_SENSOR_TO_ADC: AD_OUT1.5 D5.1 D6.2 R47.2 | length 4013
  Top Layer w20: D6.2 1537.09,1508.09 1625,1596 1723,1596 1751,1624 1751,1942 v1(1858,2049)
  Top Layer w35: D5.1 1354,1246 1414,1306 D6.2
  Bottom Layer w15: AD_OUT1.5 107.85,1510 84,1486.15 84,890.28 304.35,669.93 989.93,669.93 1124,804 1124,1045 1223.91,1144.91 D5.1
  Bottom Layer w20: v1(1858,2049) 1975,2166 R47.2
DC-LINK_SENSOR_TO_FILTER: B13.1 R43.1 R63.1 | length 481.8
  Top Layer w25: R63.1 1050,2918 1083,2885 1083,2822 R43.1
  Bottom Layer w25: R43.1 B13.1
FAULT1: PWM_OUT1.16 R20.1 R80.2 | length 3248.5
  Top Layer w20: R80.2 4501,589 5183,589 5233,639 5233,899 5189,943 4971,943 4939,975 4939,1222 5078,1361 5078,1437 5097,1456 5237,1456 5280,1499 5690.03,1499 v1(5727,1535.97)
  Bottom Layer w20: v1(5727,1535.97) 5811,1619.97 PWM_OUT1.16
  Bottom Layer w25: R20.1 4330,760 R80.2
FAULT_T1: J3.1
FAULT_T2: J3.22
FAULT_T3: J3.16
FAULT_T4: J3.25
FAULT_T5: J3.19
FAULT_T6: J3.10
FAULT_T7: J3.7
GND_CTRL: B1.10 C3.1 C4.1 C5.2 C6.2 C7.2 C8.2 DS3.2 DS4.2 DS5.2 J2.3 J3.4 J3.8 J3.11 J3.18 LVR_5_to_3V3.2 PWM_OUT1.13 Q1.1 R1.2 R5.1 R6.1 R7.1 R8.1 R9.1 R10.1 R11.1 R12.1 R13.1 R14.1 R15.1 R16.1 R17.1 X1.1 | length 13847.3
  Top Layer w15: v1(4555,3309) 4561.8,3302.2 v1(4784.8,3302.2)
  Top Layer w19: v1(6035,3144) 6217,3144 6226,3153 v1(6233,3146)
  Top Layer w25: R1.2 4300,1721 4334,1755 R12.1 R16.1 R13.1 ; R14.1 5221,2752 5303,2670 v1(5526,2670) ; R9.1 R10.1 ; R11.1 5550,2305 R5.1 5550,2105 5608,2047 v1(5766,2047) ; R8.1 5572,1162.5 R7.1
  Bottom Layer w10: J3.4 4023.9,3724.9 4051,3752 4172,3752 ; J3.18 4186.95,3737.05 4172,3752 ; J3.8 4458.7,3736.3 4443,3752 4231,3752 ; C4.1 4342.43,3863.43 4231,3752 ; 4172,3752 4231,3752
  Bottom Layer w15: J3.8 4458.7,3468.3 4555,3372 v1(4555,3309) ; v1(4784.8,3302.2) J3.11
  Bottom Layer w19: 5005.31,884 5064.31,943 5129,943 5147,961 C8.2 ; C7.2 C8.2 ; R8.1 R6.1 5231,1091 5187,1091 C8.2 ; DS5.2 5588,3068 5588,3259 5520,3327 5520,3440 5565,3485 C3.1 ; LVR_5_to_3V3.2 5701.5,3438 C3.1 ; C5.2 6217.57,3863.43 6233,3848 6233,3588 ; C6.2@6034.85,3288 C6.2 v1(6035,3144) ; v1(6233,3146) 6233,3588 ; C3.1 5654.5,3551.5 5691,3588 6233,3588
  Bottom Layer w25: R1.2 4367,1025 4451.92,1109.92 X1.1 4570,953 4639,884 5005.31,884 Q1.1 ; R17.1 R15.1 R14.1 5127,2614 5179.3,2561.7 B1.10 5395,2460 R11.1 ; v1(5526,2670) DS3.2 DS5.2 ; R7.1 5572,1383 5637,1448 5637,1558 R10.1 5660,1755 DS4.2 5989,1755 ; C4.1 C5.2 ; v1(5766,2047) 5846,2047 5923,2124 J2.3 6019.41,1988.41 5989,1958 5989,1755 ; PWM_OUT1.13 6145.59,1519.97 6153.19,1527.56 6153.19,1735.81 6134,1755 5989,1755
GND_SEN: AD_OUT1.16 B11.3 B11.5 B12.3 B12.5 B13.3 B13.5 B14.3 B14.5 B15.3 B15.5 B16.3 B16.5 C1.1 C2.2 C14.2 C15.2 C16.1 C17.1 C18.2 C19.2 C20.1 C21.1 C22.2 C23.2 C24.2 C26.2 C27.2 C28.1 C29.1 C32.2 C33.2 C34.1 C35.1 C37.2 C38.2 C39.1 C40.1 C41.2 C42.2 C43.1 C44.1 C45.2 C46.2 C47.2 C48.2 C49.2 C50.2 C51.2 C52.2 C53.2 D2.1 D4.1 D6.1 D9.1 D11.1 D13.1 DS1.2 J1.2 J4.4 J11.17 J11.18 J11.21 J11.22 R1.1 R3.1 R110.2 R111.2 R112.2 | length 28147.7
  Top Layer w15: v1(840,1485) 889,1485 910,1506 1067,1506 1108,1465 v1(1108,1135) ; v1(2238,1668) 2714,1668 v1(2769,1613) ; v1(3599,3010) 3674,2935 3674,2681 3740,2615 R111.2
  Top Layer w20: v1(464,2596) 574,2596 ; v1(681,2081) 681,2162 530,2313 530,2552 574,2596 ; v1(714,2602) 580,2602 574,2596 ; v1(1131,2079) 1227,2175 1386,2175 v1(1432,2221) ; v1(2172,2726) 2237.5,2791.5 2309.39,2791.5 2354.89,2837 v1(2566,2837) ; v1(2686,2294) v1(2855,2294)
  Top Layer w25: R3.1 1370,3156 ; v1(1301,3395) 1301,3328 1370,3259 1370,3156 ; R110.2 1529,3156 1370,3156 ; v1(2769,1613) 2832,1613 2853,1592 2853,1238 ; D4.1 2891,1070.91 2891,1128 2853,1166 2853,1238 ; v1(3901,1934) 3901,1858 3794,1751 3615,1751 3528,1664 3528,1579 3433,1484 3264,1484 3188.61,1408.61 3188.61,1310.61 3110,1232 2859,1232 2853,1238
  Bottom Layer w15: v1(2238,1668) 2238,1771.3 B11.3 ; B11.5 2615.3,1676.7 2679,1613 v1(2769,1613) ; v1(3599,3010) 3599,3097 3637,3135 4061,3135 4181,3015 C37.2 ; B16.3 3963.7,2600 4176.3,2600 B16.5
  Bottom Layer w20: C2.2 332,2874.97 332,2823 ; v1(464,2596) 417,2596 332,2511 ; C28.1 533,2500 353.85,2320.85 J1.2 332,2425.88 332,2511 ; v1(681,2081) 527,2081 419,1973 419,1876 464,1831 528,1831 676,1683 788,1683 840,1631 v1(840,1485) ; v1(714,2602) 644,2672 644,2735 682,2773 C51.2 C24.2 ; DS1.2 755,3048 724,3017 609,3017 500,2908 500,2862 461,2823 332,2823 ; C29.1 C26.2 991,2500 1145,2346 1251,2346 1286,2381 1286,2447.3 B13.3 1556.3,2505 B13.5 ; C15.2 891,2080 944,2133 1090,2133 1131,2092 v1(1131,2079) ; 1107,1252 1108,1251 v1(1108,1135) ; B12.3 1434.3,1725 B12.5 1534.3,1405.7 1544,1396 1858.91,1396 D6.1 ; J11.21 1300.18,3395.82 v1(1301,3395) ; v1(1432,2221) 1432,2110 C14.2 ; C44.1 2143,2645 2172,2674 v1(2172,2726) ; 2447,2524 2447,3152 R112.2 2594,3299 2887,3299 3040,3452 J4.4 ; v1(2566,2837) 2620,2837 2647,2810 C32.2 2851,2810 C33.2 ; B14.5 2657,2424 2686,2395 v1(2686,2294) ; v1(2855,2294) 2907.7,2294 B15.3 3043,2335 3143,2235 B15.5 3310,2235 3344,2201 3344,2075 3252,1983 C49.2 ; C50.2 C45.2 C49.2 ; C34.1 C35.1 C46.2 C49.2 ; R111.2 3898.7,2615 B16.3 ; 332,2511 332,2823
  Bottom Layer w25: AD_OUT1.16 505,1010 ; C41.2 C42.2 C43.1 602,990 582,1010 505,1010 ; C24.2 1091,2818 1091,2963 1153,3025 C27.2 1276,3090 R3.1 ; C44.1 2262.7,2568 B14.3 2519.3,2524 B14.5 ; D9.1 2214.91,1306 2118,1306 ; D11.1 2702,710 2838.09,846.09 D4.1 ; v1(2769,1613) C23.2 C53.2 2593,1458 C19.2 C21.1 C18.2 2132,1320 2118,1306 ; C34.1 3737,1934 v1(3901,1934) 3970,1934 4002,1902 4002,1848 ; R1.1 3816,1025 3797,1044 3797,1374 3751,1420 C39.1 C40.1 3777,1672 3853.91,1672 D13.1 4002,1717.91 4002,1848 ; C37.2 C38.2 4405,3015 C47.2 ; B16.5 4236,2539.7 4236,2359 C48.2 4207,2172 4207,1988 4067,1848 4002,1848 ; 505,1010 545,1050 C16.1 C52.2 C22.2 C17.1 1107,1252 C20.1 1389,1252 1512,1129 D2.1 1771.91,1129 D6.1 2118,1306
  Bottom Layer w35: C1.1 151.57,3055.39 C2.2 ; v1(681,2081) 825,2081 C15.2 ; v1(714,2602) 763,2553 C29.1 ; J11.17 J11.18 974.07,3729.07 996,3751 1224.57,3751 1300.18,3675.4 J11.21 J11.22 ; C14.2 C14.2@1434.3,2107.7
NetB11_2: B11.2 R34.1 R35.1 R36.2 | length 1221.3
  Top Layer w20: R34.1 1353,2296 1801,2296 R35.1 1982,2199 2068,2113 2129,2113 2164,2078 R36.2
  Bottom Layer w20: R36.2 2164,1963 2191,1936 B11.2
NetB11_6: B11.6 C13.2 R56.2 | length 521
  Bottom Layer w20: 2696,1836 2696,1776 2843,1629 R56.2
  Bottom Layer w25: B11.6 2696,1836 2767,1836 C13.2
NetB11_7: B11.7 C13.1 R41.1 R58.2 | length 1185.7
  Top Layer w20: v1(2768,2066) 2984,2066 3008,2042 3008,1641 3020,1629 R58.2
  Bottom Layer w20: C13.1 v1(2768,2066)
  Bottom Layer w25: B11.7 2616.3,1935 C13.1 ; R58.2 R41.1
NetB12_2: B12.2 R28.1 R29.1 R30.2 | length 1249.9
  Top Layer w20: R28.1 504,1848 624,1728 624,1664 ; R29.1 624,1565 624,1664 ; R30.2 994,1627 661,1627 624,1664
  Bottom Layer w20: R30.2 1058,1754 1129,1825 B12.2
NetB12_6: B12.6 C12.2 R31.2 | length 581.9
  Bottom Layer w20: B12.6 C12.2 1734,1725 1758,1701 1758,1511 1726,1479 R31.2
NetB12_7: B12.7 C12.1 R40.2 R50.2 | length 1113.8
  Top Layer w20: R50.2 912.67,1791.33 988,1716 1145,1716 v1(1146,1717)
  Bottom Layer w20: v1(1146,1717) 1205,1776 1347,1776 1396,1825 B12.7
  Bottom Layer w25: B12.7 C12.1 1754,1825 R40.2
NetB13_2: B13.2 R42.1 R43.2 | length 815.5
  Bottom Layer w20: R42.1 765,2685 873,2577 1028,2577 R43.2 1200,2461.3 B13.2
NetB13_6: B13.6 C25.2 R45.2 | length 668.6
  Bottom Layer w20: R45.2 1456,2705.3 B13.6
  Bottom Layer w25: B13.6 1716,2505 1746,2475 1799,2475 1805,2481 C25.2
NetB13_7: B13.7 C25.1 R47.1 R62.2 | length 681.6
  Top Layer w25: R62.2 1867,2798 R47.1
  Bottom Layer w25: B13.7 1780,2605 C25.1 1864,2689 1974,2689 R47.1
NetB14_2: B14.2 R68.1 R69.1 R70.2 | length 817.5
  Top Layer w20: R70.2 2079,2849 2145,2915 R68.1 R69.1
  Bottom Layer w20: R68.1 2312,2915 2383,2844 2383,2654 2353,2624 B14.2
NetB14_6: B14.6 C30.2 R71.2 | length 612.4
  Bottom Layer w25: B14.6 2777,2524 C30.2 2847,2530 2864,2513 2864,2417 2767,2320 2767,2236 R71.2
NetB14_7: B14.7 C30.1 R76.2 R81.1 | length 3552.1
  Top Layer w15: v1(2882,1732) 2828,1786 2527,1786 2449,1864 2449,1962 2427,1984 2236,1984 2228,1992 2228,2308 2275,2355 2803,2355 2861,2413 2861,2554 2986,2679 v1(2989,2679)
  Top Layer w25: R81.1 R76.2
  Bottom Layer w15: B14.7 2777,2624 C30.1 2888,2630 2937,2679 v1(2989,2679) ; v1(2882,1732) 2978,1732 3023,1687 3023,1456 3087,1392 3346,1392 R76.2
NetB15_2: B15.2 R82.1 R83.1 R84.2 | length 1245.9
  Top Layer w20: R84.2 3410,2810 3430,2830 R82.1
  Bottom Layer w20: B15.2 3043,2435 3276,2668 3276,2809 R84.2 3277,2849 3066,3060 R83.1
NetB15_6: B15.6 C31.2 R90.2 | length 741.5
  Bottom Layer w20: B15.6 3355,2335 3415,2275 3481,2275 3500,2294 C31.2 3637,2340 3697,2280 3788,2280 3815,2307 R90.2
NetB15_7: B15.7 C31.1 R85.1 R89.2 | length 905.6
  Top Layer w20: R89.2 R85.1
  Bottom Layer w20: B15.7 3495,2435 C31.1 3915,2440 R89.2
NetB16_2: B16.2 R96.1 R97.1 R98.2 | length 1260.2
  Top Layer w20: R97.1 R98.2
  Bottom Layer w20: R98.2 R96.1 3203.33,3027.67 3392,2839 3737,2839 3836,2740 B16.2
NetB16_6: B16.6 C36.2 R103.2 | length 345.6
  Bottom Layer w25: B16.6 C36.2 4490,2640 R103.2
NetB16_7: B16.7 C36.1 R99.1 R102.2 | length 689.3
  Top Layer w25: R99.1 4660,2602 4697.5,2639.5 R102.2
  Bottom Layer w25: B16.7 C36.1 4449,2804 4598.5,2804 R102.2
NetC22_1: C22.1 C52.1 R31.1 R32.2 R50.1 | length 978.9
  Top Layer w20: R32.2 R50.1
  Bottom Layer w20: C52.1 707.75,1436.75 767.33,1496.33 R32.2 ; R50.1 956,1563 1040,1479 R31.1
  Bottom Layer w35: C52.1 C22.1
NetC23_1: C23.1 C53.1 R39.2 R56.1 R58.1 | length 1941.2
  Top Layer w15: R39.2 1981,1695 1981,1419 2285,1115 2585,1115 2648,1178 v1(2648,1191)
  Bottom Layer w15: v1(2648,1191) 2743,1191 2769,1217 C23.1
  Bottom Layer w25: C53.1 C23.1 2919,1353 R56.1 R58.1
NetC24_1: C24.1 C51.1 R45.1 R62.1 R63.2 | length 2017.4
  Top Layer w25: R45.1 1326,2878 1421,2973 R62.1
  Bottom Layer w20: R63.2 887,2918 1188,3219 1408,3219 1486,3141 1486,3037 1550,2973 R62.1
  Bottom Layer w25: C51.1 C24.1 1154,2781 1154,2876 R45.1
NetC45_1: C45.1 C50.1 R71.1 R76.1 R77.2 | length 1458.6
  Top Layer w20: R77.2 2492,2203 R71.1 2685,2207 2760,2132 v1(2853,2132)
  Bottom Layer w20: v1(2853,2132) 2853,1911.33 C50.1 C45.1 3173.67,1752 3377,1752 3409,1720 R76.1
NetC46_1: C46.1 C49.1 R89.1 R90.1 R93.2 | length 2848.3
  Top Layer w20: v1(3514,1256) 3558,1300 3695,1300 3807,1412 3807,1662 3849.5,1704.5 3952.5,1704.5 4067,1819 4067,1988 R89.1 R90.1 3736,2080 3590,2226 R93.2
  Bottom Layer w20: C49.1 C46.1 3514,1734.33 v1(3514,1256)
NetC47_1: C47.1 C48.1 R102.1 R103.1 R106.2 | length 1913.1
  Top Layer w25: R106.2 4148,2922 4472,2922 R103.1 4600,3005 4620,2985 4620,2849 ; v1(4415,2447) 4620.06,2652.06 4620.06,2732.01 4620,2732.07 4620,2849 ; R102.1 4697.5,2871.5 4675,2849 4620,2849
  Bottom Layer w25: C48.1 v1(4415,2447) ; C47.1 4645,3057.5 R102.1
NetD_1: D.1 R21.1 | length 600.5
  Top Layer w25: R21.1 4865,925 4921,869 5134,869 v1(5135,870)
  Bottom Layer w25: v1(5135,870) 5175.77,829.23 D.1
NetD_2: D.2 Q1.2 | length 656.2
  Bottom Layer w25: Q1.2 4915.16,653.84 4941,628 5345,628 5365,648 D.2
NetDS1_1: DS1.1 R2.2 | length 345.6
  Bottom Layer w20: R2.2 514,3319 514,3146 582,3078 DS1.1
NetDS2_1: DS2.1 R3.2 | length 448.5
  Top Layer w25: R3.2 v1(976,3339)
  Bottom Layer w25: DS2.1 811,3277 873,3339 v1(976,3339) 990,3339 v1@992,3341
NetDS3_1: DS3.1 R4.2 | length 167.9
  Bottom Layer w25: DS3.1 5782,2830 R4.2
NetDS4_1: DS4.1 R113.2 | length 346.6
  Bottom Layer w25: R113.2 5651,2106 5651,2034 5709.64,1975.36 DS4.1
NetDS5_1: DS5.1 R114.2 | length 167.1
  Bottom Layer w25: DS5.1 5784,3008 R114.2
NetQ1_3: Q1.3 R80.1 | length 192.1
  Bottom Layer w25: R80.1 4820,755 Q1.3
PWM1A_DSP: B1.2 PWM_OUT1.3 R6.2 | length 2249.4
  Top Layer w20: R6.2 5297,1188 5359,1126 5359,983 5411,931 v1(5450,931)
  Bottom Layer w20: B1.2 5223,1660 5249,1634 5249,1373 R6.2 ; v1(5450,931) 5450,795 5627,618 6082,618 6181,717 6181,987 6148.03,1019.97 PWM_OUT1.3
PWM1A_TO_CONV: B1.18 J3.3 R12.2 | length 2373
  Top Layer w20: v1(4040,3310) 4040,3229 3936,3125 3936,2989 4153,2772 4153,2492 4232,2413 4232,2228 R12.2
  Bottom Layer w20: J3.3 3916,3554.28 3916,3434 v1(4040,3310)
  Bottom Layer w25: R12.2 4616,1844 4702,1844 4786,1760 B1.18
PWM1B_DSP: B1.5 PWM_OUT1.12 R9.2 | length 1827.3
  Top Layer w20: R9.2 5266,1811 5266,1622 5314,1574 5644,1574 5673,1603 5776,1603 5821,1558 5821,1413.99 v1(5727,1319.99)
  Top Layer w25: R9.2 R9.2@5409,1945
  Bottom Layer w20: v1(5727,1319.99) 5826.98,1419.97 PWM_OUT1.12
  Bottom Layer w25: B1.5 5241,1960 5277,1996 5349,1996 R9.2
PWM1B_TO_CONV: B1.15 J3.20 R15.2 | length 2157.1
  Top Layer w15: v1(4397,3290) 4453,3234 4753,3234 4935,3052 R15.2
  Top Layer w19: v1(4925,2620) 4925,2824 4984.5,2883.5 R15.2
  Bottom Layer w15: v1(4397,3290) 4429,3322 4429,3371 4404.35,3395.65 J3.20
  Bottom Layer w19: B1.15 4961,2154.3 4961,2584 v1(4925,2620)
PWM2A_DSP: B1.3 PWM_OUT1.2 R7.2 | length 1431.9
  Top Layer w20: R7.2 5572,958 5610.03,919.97 v1(5738.97,919.97)
  Bottom Layer w20: B1.3 5243,1760 5329,1674 5329,1475 5368,1436 5368,1229 R7.2 ; v1(5738.97,919.97) PWM_OUT1.2
PWM2A_TO_CONV: B1.17 J3.14 R13.2 | length 3453.2
  Top Layer w20: v1(3863,3315) 3863,2584 3679,2400 3679,2296 3774,2201 4136,2201 4427,1910 4638,1910 4675,1947 R13.2
  Bottom Layer w20: J3.14 3613.89,3666.89 3564,3617 3564,3396 3645,3315 v1(3863,3315)
  Bottom Layer w25: R13.2 4760,1970 4760,1895 4795,1860 B1.17
PWM2B_DSP: B1.6 PWM_OUT1.11 R10.2 | length 1621.5
  Top Layer w25: R10.2 5812,1945 5855,1902 v1(6110,1902)
  Bottom Layer w25: B1.6 5435,2060 R10.2 ; PWM_OUT1.11 6173.97,1419.97 6203.19,1449.19 6203.19,1810.81 v1@6108,1906
PWM2B_TO_CONV: B1.14 J3.23 R16.2 | length 2162.6
  Top Layer w20: R16.2 v1(4540,2418)
  Bottom Layer w15: v1(4540,2418) 4540,2569 4608,2637 4727,2637 4769,2679 4769,3135 4730.45,3173.55 J3.23
  Bottom Layer w25: R16.2 4645,2160 B1.14
PWM3A_DSP: B1.4 PWM_OUT1.1 R8.2 | length 2062.2
  Bottom Layer w20: B1.4 5314,1860 5471,1703 5471,1361.5 R8.2 5434.5,1290.5 5640,1085 5640,897 5640,742 5675,707 6036,707 6086.16,757.16 PWM_OUT1.1
PWM3A_TO_CONV: B1.16 J3.17 R14.2 | length 2768.4
  Top Layer w15: v1(4119,3382) 4808,3382 4865,3325 4865,3200 4927,3138 5041,3138 R14.2
  Top Layer w20: v1(5049,2622) 5049,2820 5127,2898 R14.2
  Bottom Layer w10: J3.17 4076,3664.64 4076,3425 v1(4119,3382)
  Bottom Layer w20: B1.16 4947,1960 5049,2062 v1(5049,2622)
PWM3B_DSP: B1.7 PWM_OUT1.10 R11.2 | length 1853.4
  Top Layer w20: R11.2 5461,2094 5461,1869 5652,1678 5836,1678 5895,1619 5895,1380 v1(5727,1212)
  Bottom Layer w20: v1(5727,1212) 5834.97,1319.97 PWM_OUT1.10 PWM_OUT1.10@5985.19,1319
  Bottom Layer w25: B1.7 5184.3,2155 R11.2
PWM3B_TO_CONV: B1.13 J3.12 R17.2 | length 1384.6
  Top Layer w20: v1(4772,2502) 4773,2503 4773,2860 4842,2929 R17.2
  Bottom Layer w20: v1(4772,2502) 4772,2354.7 B1.13 ; R17.2 4842,3266 4893.5,3317.5 J3.12
PWM_ENABLE: B1.1 B1.19 X1.2 | length 1249.8
  Bottom Layer w25: X1.2 4442.04,1294.96 4395,1342 4395,1509 4546,1660 B1.19 4980,1660 5080,1560 B1.1
PWM_T7: J3.9
RELAY: J3.13
RESET_TO_CONVERTER: J3.2 R5.2 SW1.3 | length 2610.9
  Top Layer w15: v1(3804,3395) 3842,3433 4851,3433 4917,3367 4917,3267 v1(4989.58,3194.42)
  Bottom Layer w15: v1(4989.58,3194.42) SW1.3
  Bottom Layer w20: v1(3804,3395) 3804,3552.58 J3.2
  Bottom Layer w25: SW1.3 5193.58,3194.42 5235,3153 5235,2770 R5.2
V_AB_TO_ADAPTATION: J4.1 R69.2 R110.1 | length 1788.2
  Top Layer w20: R110.1 1958,3209 2084,3209 2167,3126 2332,3126 2408,3050 R69.2
  Bottom Layer w20: R110.1 1867,3191 2109,3433 2369,3433 2440,3504 J4.1
V_AB_TO_ADC: AD_OUT1.2 D8.1 D9.2 R81.2 | length 5295.3
  Top Layer w25: D8.1 2577.91,850.09 2729,699 3356,699 3409,752 R81.2
  Bottom Layer w15: AD_OUT1.2 260.22,1781 238.22,1803 36,1803 -91.18,1675.82 -91.18,938.18 277,570 2220,570 2259,609 D9.2 D8.1
V_AB_TO_FILTER: B14.1 R70.1 R77.1 | length 1593.6
  Top Layer w20: R70.1 1942,3055 1942,2810 2059,2693 2059,2437 2074,2422 R77.1
  Bottom Layer w20: R70.1 2036,2966 2278,2724 B14.1
V_BC_TO_ADAPTATION: J4.2 R83.2 R111.1 | length 2357.9
  Top Layer w20: v1(2592,3362) 2592,3105 2637,3060 R83.2 2748,3138 3268,3138 3413,3283 3757,3283 3790,3250 3790,2950 R111.1
  Bottom Layer w20: v1(2592,3362) 2592,3425 2641,3474 2641,3769 J4.2
V_BC_TO_ADC: AD_OUT1.4 D10.1 D11.2 R85.2 | length 5658.5
  Top Layer w25: v1(609,1475) 620,1486 632,1474 724,1474 789,1409 789,1201 933.88,1056.12 1745.88,1056.12 1801,1001 1801,769 1860,710 D11.2 2160,710 2251.5,618.5 3422,618.5 3516,712.5 3516,929 3597,1010 D10.1 3699.91,1171.91 4037,1509 4037,1693 4140,1796 R85.2
  Bottom Layer w25: AD_OUT1.4 472.53,1610 607.53,1475 v1(609,1475)
V_BC_TO_FILTER: B15.1 R84.1 R93.1 | length 1549.2
  Top Layer w20: R84.1 3099,2810 3375,2534 3476,2534 3517,2575 3517,2682 3590,2755 R93.1
  Bottom Layer w20: B15.1 3019,2535 3112,2628 3112,2791 3093,2810 R84.1
V_CA_TO_ADAPTATION: J4.3 R97.2 R112.1 | length 1473.7
  Top Layer w20: v1(2287,3336) 2435,3336 2529,3430 2673,3430 ; R97.2 2771,3215 2789,3233 2789,3314 2673,3430 ; v1(2837,3449) 2800.5,3485.5 2728.5,3485.5 2673,3430
  Bottom Layer w20: R112.1 2210,3259 v1(2287,3336) ; v1(2837,3449) 2840,3452 J4.3
V_CA_TO_ADC: AD_OUT1.6 D12.1 D13.2 R99.2 | length 6908.4
  Top Layer w25: v1(470,1510) 470,1445 376.5,1351.5 376.5,667.5 480.5,563.5 3580.5,563.5 3778,761 3778,1135 3852.09,1209.09 D13.2 3905,1141 3931,1115 4094,1115 4110,1131 D12.1 ; D13.2@3915,1209.09 D13.2@3925,1199.09
  Bottom Layer w25: AD_OUT1.6 v1(470,1510) ; D12.1 4110,1398 4232,1520 4232,1864 4317,1949 4317,2084 4493,2260 R99.2
V_CA_TO_FILTER: B16.1 R98.1 R106.1 | length 639.7
  Top Layer w20: R98.1 3643.33,3075 R106.1
  Bottom Layer w20: R106.1 3695,3014 3727,2982 3830,2982 3923.7,2888.3 B16.1
pads on no net: AD_OUT1.7 AD_OUT1.8 AD_OUT1.9 AD_OUT1.10 AD_OUT1.11 AD_OUT1.12 AD_OUT1.13 AD_OUT1.14 B1.8 B1.9 B1.11 B1.12 J3.5 J3.26 J3.27 J11.1 J11.5 J11.6 J11.7 J11.8 J11.9 J11.10 J11.11 J11.12 J11.13 J11.19 J11.20 J11.26 J11.27 LVR_5_to_3V3.3 LVR_5_to_3V3.4 PWM_OUT1.4 PWM_OUT1.5 PWM_OUT1.6 PWM_OUT1.7 PWM_OUT1.8 PWM_OUT1.9 PWM_OUT1.15 SW1.2 SW1.4

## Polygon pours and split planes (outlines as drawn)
GND_SEN on Top Layer "Top Layer-No Net1" (solid, remove dead copper, pour order 8): -144.88,505 6300,505 6300,4000 -144.88,4000
GND_CTRL on Top Layer "Top Layer-No Net" (solid, remove dead copper, pour order 3): -144.88,505 6300,505 6300,4000 -144.88,4000
GND_SEN on Bottom Layer "Top Layer-No Net3" (solid, remove dead copper, pour order 12): -144.88,505 6300,505 6300,4000 -144.88,4000
GND_CTRL on Bottom Layer "Top Layer-No Net2" (solid, remove dead copper, pour order 10): -144.88,505 6300,505 6300,4000 -144.88,4000

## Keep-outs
Keep-Out Layer:
  lines w32: -144.88,505 -144.88,4000 6300,4000 6300,1525 6300,505 -144.88,505

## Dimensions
6300,505 to 6300,4000 on Top Layer
-144.88,505 to 6300,505 on Top Layer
